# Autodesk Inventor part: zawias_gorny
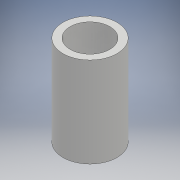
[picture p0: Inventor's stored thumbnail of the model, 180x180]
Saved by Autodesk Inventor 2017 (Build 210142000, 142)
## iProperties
Created: 2020-09
Part Number: zawias_gorny
Material: Generic
Document SubType Name: Modeling
Designer: WindowsX
Density: 1 g/cm^3
Appearance: Default
Author: WindowsX
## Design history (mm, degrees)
sketch "Szkic1"
  geometry: C1 r 15 at (0, 0); 1 further point
  constraints: 1 centre point, 1 coincident
  dimensions: "d0" = 30 diameter of C1
extrude "Wyciągnięcie proste1" new body sketch "Szkic1" distance "d1" = 50; taper "d2" = 0 deg
sketch "Szkic2"
  geometry: C1 r 11 at (0, 0); 1 further point
  constraints: 1 centre point, 1 coincident
  dimensions: "d3" = 22 diameter of C1
extrude "Wyciągnięcie proste2" cut sketch "Szkic2" distance "d4" = 40; taper "d5" = 0 deg
node "Bryła1"
